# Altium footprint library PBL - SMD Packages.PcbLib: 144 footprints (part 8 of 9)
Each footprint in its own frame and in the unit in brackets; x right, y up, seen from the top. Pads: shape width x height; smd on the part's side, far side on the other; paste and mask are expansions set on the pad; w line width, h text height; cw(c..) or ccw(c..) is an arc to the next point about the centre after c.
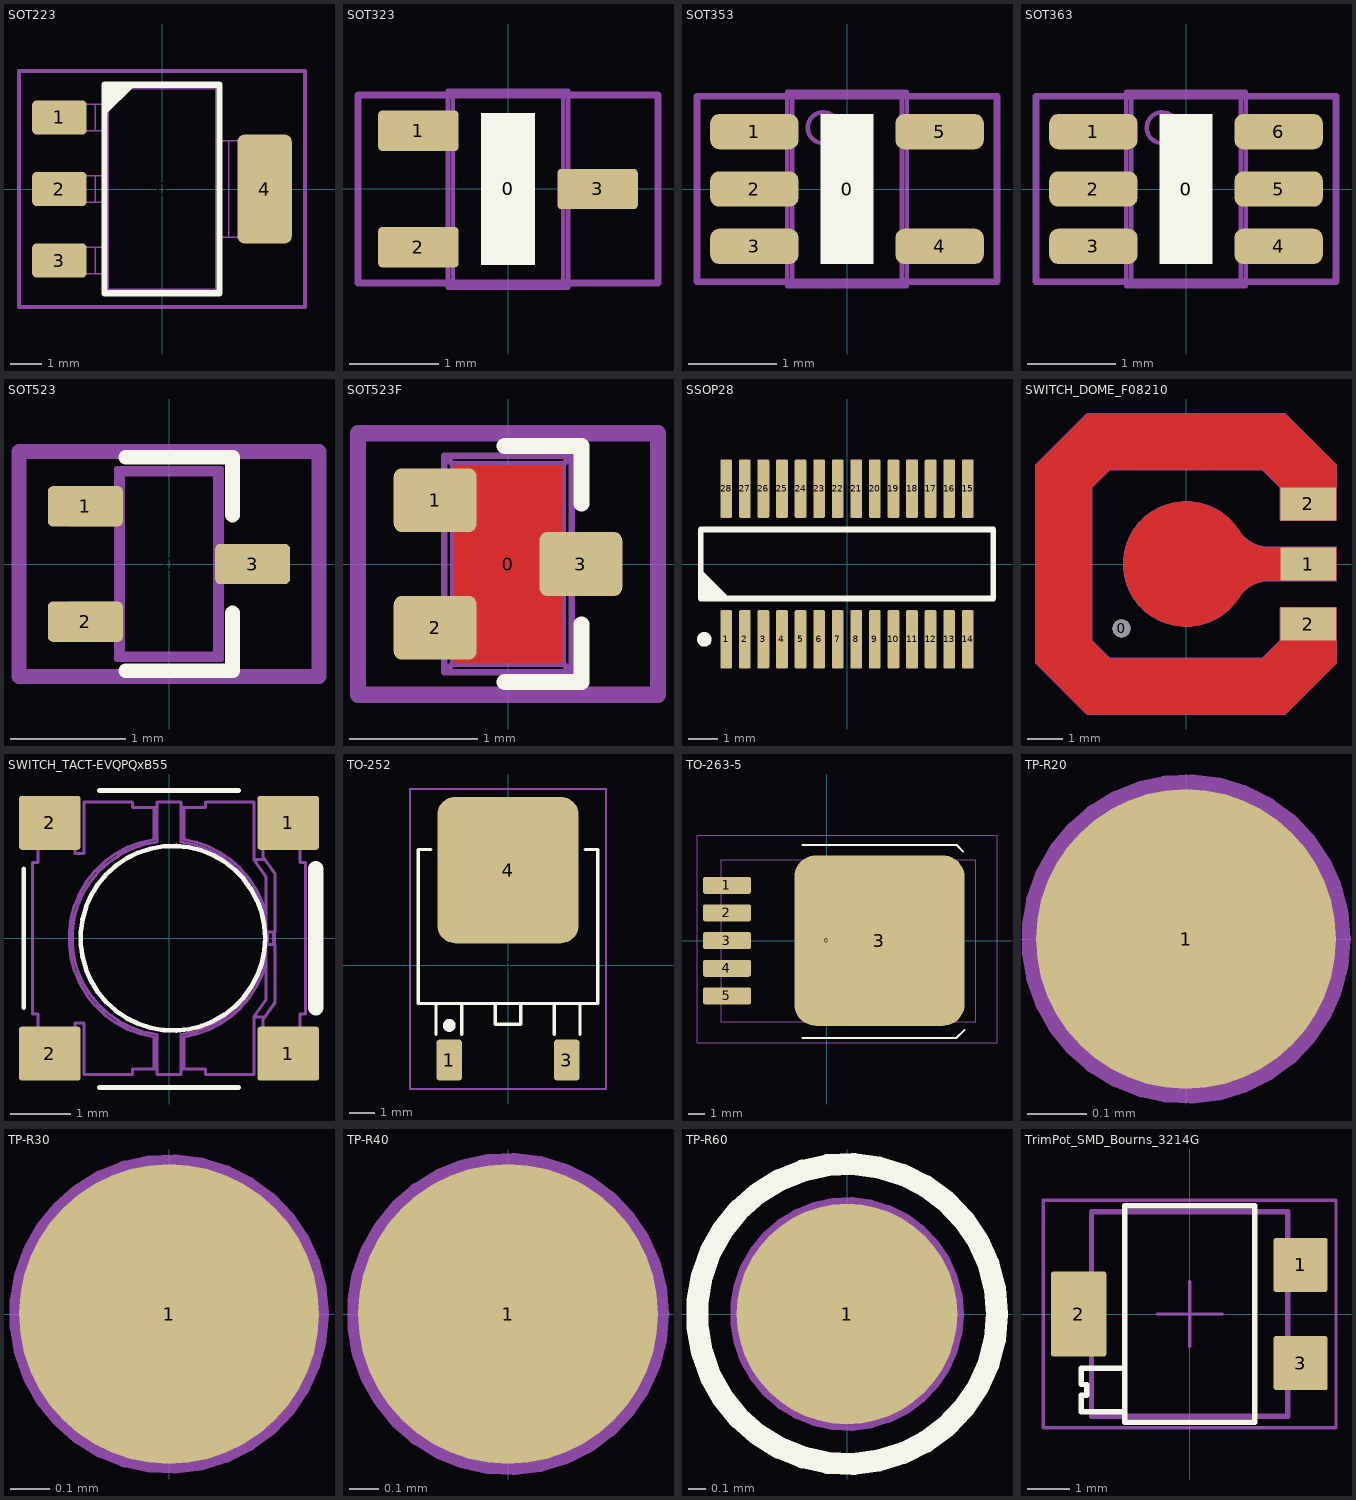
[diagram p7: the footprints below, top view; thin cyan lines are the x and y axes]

## SOT223 [mm] "SOT223 /SC-73"
height 1.524
pads (5):
  round 1 on Mech15: 0(0,0)
  rrect25% 1.75x1.1 smd: 1(-3.3,2.3) 2(-3.3,0) 3(-3.3,-2.3)
  rrect25% 1.75x3.5 smd: 4(3.3,0)
Top Overlay:
  region: -1.85,3.35 -0.85,3.35 -1.85,2.35
  lines w0.2: -1.85,-3.35 1.85,-3.35 1.85,3.35 -1.85,3.35 -1.85,-3.35
13 - 3D Top Side:
  lines w0.05: -3.186,-2.72 -3.186,-1.88 ; -3.186,-0.42 -3.186,0.42 ; -3.186,1.88 -3.186,2.72 ; -3.062,-2.72 -3.062,-1.88 ; -3.062,-0.42 -3.062,0.42 ; -3.062,1.88 -3.062,2.72 ; -2.506,-2.72 -2.506,-1.88 ; -2.506,-0.42 -2.506,0.42 ; -2.506,1.88 -2.506,2.72 ; -2.152,-2.72 -2.152,-1.88 ; -2.152,-0.42 -2.152,0.42 ; -2.152,1.88 -2.152,2.72 ; -1.85,-2.72 -1.85,-3.35 ; -1.85,-1.88 -1.85,-0.42 ; -1.85,0.42 -1.85,1.88 ; -1.85,2.72 -1.85,3.35 ; 1.85,-1.55 1.85,-3.35 ; 1.85,1.55 1.85,3.35 ; 2.152,-1.55 2.152,1.55 ; 2.506,-1.55 2.506,1.55 ; 3.062,-1.55 3.062,1.55 ; 3.186,-1.55 3.186,1.55 ; -1.85,-3.35 1.85,-3.35 ; -1.85,-3.35 -1.731,-3.231 ; -1.85,3.35 1.85,3.35 ; -1.85,3.35 -1.731,3.231 ; -1.731,-3.231 -1.731,3.231 ; -1.731,-3.231 1.731,-3.231 ; -1.731,3.231 1.731,3.231 ; 1.731,-3.231 1.731,3.231 ; 1.731,-3.231 1.85,-3.35 ; 1.731,3.231 1.85,3.35 ; -3.65,-2.72 -1.829,-2.72 -1.829,-1.88 -3.65,-1.88 -3.65,-2.72 ; -3.65,-0.42 -1.829,-0.42 -1.829,0.42 -3.65,0.42 -3.65,-0.42 ; -3.65,1.88 -1.829,1.88 -1.829,2.72 -3.65,2.72 -3.65,1.88 ; 1.829,-1.55 1.829,1.55 3.65,1.55 3.65,-1.55 1.829,-1.55
15 - Top Courtyards:
  lines w0.127: -4.6,-3.8 4.6,-3.8 4.6,3.8 -4.6,3.8 -4.6,-3.8
3D body "SOT223-4.STEP": height 1.8, standoff 0, extent -3.65,-3.35 3.65,3.35

## SOT323 [mm] "Small outline 2.1mm L x 1.25mm W x 1.1mm H; 3 lead SC70, EIAJ SC-70, SOT323"
height 1.1
pads (4):
  round 0.5 on Mech15: 0(0,0)
  rrect20% 0.9x0.45 smd: 1(-1,0.65) 2(-1,-0.65) 3(1,0)
Top Overlay:
  rectangle: -0.3,-0.85 0.3,0.85
  text "." at -1.875,0.65 h0.1
13 - 3D Top Side:
  lines w0.05: -1.028,-0.8 -1.028,-0.5 ; -1.028,0.5 -1.028,0.8 ; -0.937,-0.8 -0.937,-0.5 ; -0.937,0.5 -0.937,0.8 ; -0.925,-0.8 -0.925,-0.5 ; -0.925,0.5 -0.925,0.8 ; 0.925,-0.15 0.925,0.15 ; 0.937,-0.15 0.937,0.15 ; 1.028,-0.15 1.028,0.15 ; -0.675,-1.1 0.675,-1.1 ; -0.675,-1.1 -0.675,1.1 ; -0.675,-1.1 -0.619,-1.044 ; -0.675,1.1 0.675,1.1 ; -0.675,1.1 -0.619,1.043 ; -0.619,-1.044 0.619,-1.044 ; -0.619,-1.044 -0.619,1.043 ; -0.619,1.043 0.619,1.043 ; 0.619,-1.044 0.675,-1.1 ; 0.619,-1.044 0.619,1.043 ; 0.619,1.043 0.675,1.1 ; 0.675,-1.1 0.675,1.1 ; -1.2,-0.8 -1.2,-0.5 -0.654,-0.5 -0.654,-0.8 -1.2,-0.8 ; -1.2,0.5 -1.2,0.8 -0.654,0.8 -0.654,0.5 -1.2,0.5 ; 0.654,-0.15 1.2,-0.15 1.2,0.15 0.654,0.15 0.654,-0.15
15 - Top Courtyards:
  lines w0.076: -1.675,-1.05 -1.675,1.05 1.675,1.05 1.675,-1.05 -1.675,-1.05
3D body "SOT323.STEP": height 1.1, standoff 0, extent -1.2,-1.1 1.2,1.1

## SOT353 [mm] "Small outline 2.1mm L x 1.25mm W x 1mm H; 5LD SC-70; SC-88A"
height 1.1
pads (6):
  round 0.5 on Mech15: 0(0,0)
  rrect50% 1x0.4 smd: 1(-1.05,0.65) 2(-1.05,0) 3(-1.05,-0.65) 4(1.05,-0.65) 5(1.05,0.65)
Top Overlay:
  rectangle: -0.3,-0.85 0.3,0.85
  text "." at -2.025,0.65 h0.1
Top Solder:
  rectangle: -1.397,-0.762 -0.635,0.762
13 - 3D Top Side:
  circle w0.05: c-0.27,0.695 r0.175
  lines w0.05: -1.028,-0.8 -1.028,-0.5 ; -1.028,-0.15 -1.028,0.15 ; -1.028,0.5 -1.028,0.8 ; -0.937,-0.8 -0.937,-0.5 ; -0.937,-0.15 -0.937,0.15 ; -0.937,0.5 -0.937,0.8 ; -0.925,-0.8 -0.925,-0.5 ; -0.925,-0.15 -0.925,0.15 ; -0.925,0.5 -0.925,0.8 ; 0.925,-0.8 0.925,-0.5 ; 0.925,0.5 0.925,0.8 ; 0.937,-0.8 0.937,-0.5 ; 0.937,0.5 0.937,0.8 ; 1.028,-0.8 1.028,-0.5 ; 1.028,0.5 1.028,0.8 ; -0.675,-1.1 0.675,-1.1 ; -0.675,-1.1 -0.675,1.1 ; -0.675,-1.1 -0.619,-1.044 ; -0.675,1.1 0.675,1.1 ; -0.675,1.1 -0.619,1.044 ; -0.619,-1.044 0.619,-1.044 ; -0.619,-1.044 -0.619,1.044 ; -0.619,1.044 0.619,1.044 ; 0.619,-1.044 0.675,-1.1 ; 0.619,-1.044 0.619,1.044 ; 0.619,1.044 0.675,1.1 ; 0.675,-1.1 0.675,1.1 ; -1.2,-0.8 -1.2,-0.5 -0.654,-0.5 -0.654,-0.8 -1.2,-0.8 ; -1.2,-0.15 -1.2,0.15 -0.654,0.15 -0.654,-0.15 -1.2,-0.15 ; -1.2,0.5 -1.2,0.8 -0.654,0.8 -0.654,0.5 -1.2,0.5 ; 0.654,-0.8 1.2,-0.8 1.2,-0.5 0.654,-0.5 0.654,-0.8 ; 0.654,0.5 1.2,0.5 1.2,0.8 0.654,0.8 0.654,0.5
15 - Top Courtyards:
  lines w0.076: -1.7,-1.05 1.7,-1.05 1.7,1.05 -1.7,1.05 -1.7,-1.05
3D body "SOT353.STEP": height 1.1, standoff 0, extent -1.2,-1.1 1.2,1.1

## SOT363 [mm] "Small outline 2.1mm L x 1.25mm W x 1mm H"
height 1
pads (7):
  round 0.5 on Mech15: 0(0,0)
  rrect50% 1x0.4 smd: 1(-1.05,0.65) 2(-1.05,0) 3(-1.05,-0.65) 4(1.05,-0.65) 5(1.05,0) 6(1.05,0.65)
Top Overlay:
  rectangle: -0.3,-0.85 0.3,0.85
  text "." at -2.025,0.65 h0.1
Top Solder:
  region: 1.397,0.762 0.635,0.762 0.635,-0.762 1.397,-0.762
  rectangle: -1.397,-0.762 -0.635,0.762
13 - 3D Top Side:
  circle w0.05: c-0.27,0.695 r0.175
  lines w0.05: -1.028,-0.8 -1.028,-0.5 ; -1.028,-0.15 -1.028,0.15 ; -1.028,0.5 -1.028,0.8 ; -0.937,-0.8 -0.937,-0.5 ; -0.937,-0.15 -0.937,0.15 ; -0.937,0.5 -0.937,0.8 ; -0.925,-0.8 -0.925,-0.5 ; -0.925,-0.15 -0.925,0.15 ; -0.925,0.5 -0.925,0.8 ; 0.925,-0.8 0.925,-0.5 ; 0.925,-0.15 0.925,0.15 ; 0.925,0.5 0.925,0.8 ; 0.937,-0.8 0.937,-0.5 ; 0.937,-0.15 0.937,0.15 ; 0.937,0.5 0.937,0.8 ; 1.028,-0.8 1.028,-0.5 ; 1.028,-0.15 1.028,0.15 ; 1.028,0.5 1.028,0.8 ; -0.675,-1.1 -0.619,-1.044 ; -0.675,-1.1 -0.675,1.1 ; -0.675,-1.1 0.675,-1.1 ; -0.675,1.1 -0.619,1.044 ; -0.675,1.1 0.675,1.1 ; -0.619,-1.044 -0.619,1.044 ; -0.619,-1.044 0.619,-1.044 ; -0.619,1.044 0.619,1.044 ; 0.619,-1.044 0.619,1.044 ; 0.619,-1.044 0.675,-1.1 ; 0.619,1.044 0.675,1.1 ; 0.675,-1.1 0.675,1.1 ; -1.2,-0.8 -0.654,-0.8 -0.654,-0.5 -1.2,-0.5 -1.2,-0.8 ; -1.2,-0.15 -0.654,-0.15 -0.654,0.15 -1.2,0.15 -1.2,-0.15 ; -1.2,0.5 -0.654,0.5 -0.654,0.8 -1.2,0.8 -1.2,0.5 ; 0.654,-0.8 0.654,-0.5 1.2,-0.5 1.2,-0.8 0.654,-0.8 ; 0.654,-0.15 0.654,0.15 1.2,0.15 1.2,-0.15 0.654,-0.15 ; 0.654,0.5 0.654,0.8 1.2,0.8 1.2,0.5 0.654,0.5
15 - Top Courtyards:
  lines w0.076: -1.7,-1.05 1.7,-1.05 1.7,1.05 -1.7,1.05 -1.7,-1.05
3D body "SOT363.STEP": height 1.1, standoff 0, extent -1.2,-1.1 1.2,1.1

## SOT523 [mm] "3 Lead SC75; EIAJ-SC75; SOT523; SOT416?"
height 0.9
pads (4):
  round 0.254 on Mech15: 0(0,0)
  rrect25% 0.65x0.35 smd: 1(-0.725,0.5) 2(-0.725,-0.5) 3(0.725,0)
Top Overlay:
  lines w0.127: -0.375,-0.925 0.55,-0.925 0.55,-0.425 ; -0.375,0.925 0.55,0.925 0.55,0.425
  text "." at -1.455,0.5 h0.05
13 - 3D Top Side:
  lines w0.05: -0.669,-0.65 -0.669,-0.35 ; -0.669,0.35 -0.669,0.65 ; -0.623,-0.65 -0.623,-0.35 ; -0.623,0.35 -0.623,0.65 ; -0.61,-0.65 -0.61,-0.35 ; -0.61,0.35 -0.61,0.65 ; 0.61,-0.15 0.61,0.15 ; 0.623,-0.15 0.623,0.15 ; 0.669,-0.15 0.669,0.15 ; -0.45,-0.825 0.45,-0.825 ; -0.45,-0.825 -0.45,0.825 ; -0.45,-0.825 -0.408,-0.783 ; -0.45,0.825 0.45,0.825 ; -0.45,0.825 -0.408,0.783 ; -0.408,-0.783 0.408,-0.783 ; -0.408,-0.783 -0.408,0.783 ; -0.408,0.783 0.408,0.783 ; 0.408,-0.783 0.45,-0.825 ; 0.408,-0.783 0.408,0.783 ; 0.408,0.783 0.45,0.825 ; 0.45,-0.825 0.45,0.825 ; -0.85,-0.65 -0.85,-0.35 -0.429,-0.35 -0.429,-0.65 -0.85,-0.65 ; -0.85,0.35 -0.85,0.65 -0.429,0.65 -0.429,0.35 -0.85,0.35 ; 0.429,-0.15 0.85,-0.15 0.85,0.15 0.429,0.15 0.429,-0.15
15 - Top Courtyards:
  lines w0.127: -1.3,-0.975 1.3,-0.975 1.3,0.975 -1.3,0.975 -1.3,-0.975
3D body "SOT523.STEP": height 0.9, standoff 0, extent -0.85,-0.825 0.85,0.825

## SOT523F [mm] "3 Lead SC89; EIAJ-SC89; SOT523F"
height 0.8
pads (4):
  round 0.254 on Mech15: 0(0,0)
  rrect25% 0.65x0.5 smd: 1(-0.57,0.5) 2(-0.57,-0.5) 3(0.57,0)
Top Layer:
  pour cut-out: -0.425,0.775 0.425,0.775 0.425,-0.775 -0.425,-0.775
Top Overlay:
  lines w0.127: -0.025,-0.925 0.575,-0.925 0.575,-0.475 ; -0.025,0.925 0.575,0.925 0.575,0.475
  text "." at -1.3,0.5 h0.05
13 - 3D Top Side:
  lines w0.05: -0.499,-0.675 -0.499,-0.849 ; -0.499,-0.325 -0.499,0.325 ; -0.499,0.675 -0.499,0.849 ; 0.499,-0.175 0.499,-0.849 ; 0.499,0.175 0.499,0.849 ; -0.499,-0.849 0.499,-0.849 ; -0.499,-0.849 -0.43,-0.78 ; -0.499,0.849 0.499,0.849 ; -0.499,0.849 -0.43,0.78 ; -0.43,-0.78 0.43,-0.78 ; -0.43,-0.78 -0.43,0.78 ; -0.43,0.78 0.43,0.78 ; 0.43,-0.78 0.43,0.78 ; 0.43,-0.78 0.499,-0.849 ; 0.43,0.78 0.499,0.849 ; -0.85,-0.675 -0.85,-0.325 -0.483,-0.325 -0.483,-0.675 -0.85,-0.675 ; -0.85,0.325 -0.85,0.675 -0.483,0.675 -0.483,0.325 -0.85,0.325 ; 0.483,-0.175 0.85,-0.175 0.85,0.175 0.483,0.175 0.483,-0.175
15 - Top Courtyards:
  lines w0.127: -1.175,-1.025 1.175,-1.025 1.175,1.025 -1.175,1.025 -1.175,-1.025
3D body "SOT523F.STEP": height 0.8, standoff 0, extent -0.85,-0.849 0.85,0.849

## SSOP28 [mm] "SSOP; 28 Leads; Body Width 3.9 mm; Pitch 0.635 mm"
height 1.75
pads (28):
  rrect25% 0.4x2 smd: 1(-4.127,-2.575) 2(-3.492,-2.575) 3(-2.857,-2.575) 4(-2.222,-2.575) 5(-1.587,-2.575) 6(-0.953,-2.575) 7(-0.318,-2.575) 8(0.318,-2.575) 9(0.953,-2.575) 10(1.587,-2.575) 11(2.222,-2.575) 12(2.857,-2.575) 13(3.492,-2.575) 14(4.127,-2.575) 15(4.127,2.575) 16(3.492,2.575) 17(2.857,2.575) 18(2.222,2.575) 19(1.587,2.575) 20(0.953,2.575) 21(0.318,2.575) 22(-0.318,2.575) 23(-0.953,2.575) 24(-1.587,2.575) 25(-2.222,2.575) 26(-2.857,2.575) 27(-3.492,2.575) 28(-4.127,2.575)
Top Overlay:
  circle w0.25: c-4.878,-2.575 r0.125
  region: -5,-1.175 -5,-0.175 -4,-1.175
  lines w0.2: -5,-1.175 5,-1.175 5,1.175 -5,1.175 -5,-1.175

## SWITCH_DOME_F08210 [mm] "Snaptron F08210 dome switch"
height 0.5
pads (4):
  round 0.508 hole 0.508 unplated: 0(-1.8,-1.8)
  rect 1.55x0.92 smd paste-0.8: 1(3.415,0) 2(3.415,-1.68) 2(3.415,1.68)
Top Layer:
  region: -2.77,-4.19 -4.19,-2.77 -4.19,2.77 -2.77,4.19 2.77,4.19 4.19,2.77 4.19,1.22 2.64,1.22 2.64,2.128 2.128,2.64 -2.128,2.64 -2.64,2.128 -2.64,-2.128 -2.128,-2.64 2.128,-2.64 2.64,-2.128 2.64,-1.22 4.19,-1.22 4.19,-2.77 2.77,-4.19
  region: 1.472,-0.927 1.372,-1.086 1.109,-1.354 0.795,-1.559 0.444,-1.693 0.073,-1.749 -0.302,-1.724 -0.663,-1.62 -0.993,-1.441 -1.278,-1.196 -1.503,-0.896 -1.66,-0.555 -1.74,-0.188 -1.74,0.188 -1.66,0.555 -1.503,0.896 -1.278,1.196 -0.993,1.441 -0.663,1.62 -0.302,1.724 0.073,1.749 0.444,1.693 0.795,1.559 1.109,1.354 1.372,1.086 1.472,0.927 1.546,0.825 1.729,0.652 1.949,0.531 2.193,0.468 2.319,0.46 4.19,0.46 4.19,-0.46 2.319,-0.46 2.193,-0.468 1.949,-0.531 1.729,-0.652 1.546,-0.825
Mechanical 3:
  lines w0.05: -4.19,-2.77 -4.19,2.77 -2.77,4.19 2.77,4.19 4.19,2.77 4.19,1.22 2.64,1.22 2.64,2.128 2.128,2.64 -2.128,2.64 -2.64,2.128 -2.64,-2.128 -2.128,-2.64 2.128,-2.64 2.64,-2.128 2.64,-1.22 4.19,-1.22 4.19,-2.77 2.77,-4.19 -2.77,-4.19 -4.19,-2.77 ; 1.472,-0.927 cw(c0,0) 1.472,0.927 ccw(c2.319,1.46) 2.319,0.46 4.19,0.46 4.19,-0.46 2.319,-0.46 ccw(c2.319,-1.46) 1.472,-0.927
3D body "Snap Dome F08210.STEP": height 0.48, standoff 0, extent -3.546,-3.546 3.546,3.546

## SWITCH_TACT-EVQPQxB55 [mil] "Panasonic SMD tact switch 4.5x4.5x0.55mm, EVQPQxB55"
height 21.65
pads (4):
  rrect10% 40x35 smd: 1(77.5,-75) 1(77.5,75) 2(-77.5,-75) 2(-77.5,75)
Top Overlay:
  circle w3: c2.5,0 r60
  lines w3: -94.5,-45.28 -94.5,45.28 ; -45.28,-97 45.28,-97 ; -45.28,96 45.28,96
  lines w10: 95.5,-45.28 95.5,45.28
13 - 3D Top Side:
  lines w1.97: -85.04,-84.12 -61.02,-84.12 ; -85.04,-79.15 -61.02,-79.15 ; -85.04,-77.22 -61.02,-77.22 ; -85.04,-68.45 -61.02,-68.45 ; -85.04,-66.52 -61.02,-66.52 ; -85.04,-62.25 -61.02,-62.25 ; -85.04,-58.68 -61.02,-58.68 ; -85.04,58.68 -61.02,58.68 ; -85.04,62.25 -61.02,62.25 ; -85.04,66.52 -61.02,66.52 ; -85.04,68.45 -61.02,68.45 ; -85.04,77.22 -61.02,77.22 ; -85.04,79.15 -61.02,79.15 ; -85.04,84.12 -61.02,84.12 ; -9.84,-85.04 -9.84,-64.21 cw(c0,0) -9.84,64.21 -9.84,85.04 ; -7.87,-85.04 -23.62,-85.04 -23.62,-88.58 -55.12,-88.58 -55.12,-55.12 -61.02,-55.12 -61.02,-86.61 -85.04,-86.61 -85.04,-49.21 -88.58,-49.21 -88.58,49.21 -85.04,49.21 -85.04,86.61 -61.02,86.61 -61.02,55.12 -55.12,55.12 -55.12,88.58 -23.62,88.58 -23.62,85.04 -7.87,85.04 ; -7.87,-62.5 -7.87,-88.58 7.87,-88.58 7.87,-62.5 ; -7.87,62.5 -7.87,88.58 7.87,88.58 7.87,62.5 ; -7.81,-62.51 cw(c0,0) -7.81,62.51 ; 7.81,-62.51 ccw(c0,0) 7.81,62.51 ; 7.87,-85.04 23.62,-85.04 23.62,-88.58 55.12,-88.58 55.12,-51.29 62.99,-40.04 62.99,40.04 55.12,51.29 55.12,88.58 23.62,88.58 23.62,85.04 7.87,85.04 ; 9.84,-85.04 9.84,-64.21 ccw(c0,0) 62.99,-15.87 ; 9.84,85.04 9.84,64.21 cw(c0,0) 62.99,15.87 ; 55.19,-51.18 62.4,-51.18 ; 55.19,51.18 62.4,51.18 ; 61.02,-84.12 85.04,-84.12 ; 61.02,-79.15 85.04,-79.15 ; 61.02,-77.22 85.04,-77.22 ; 61.02,-68.45 85.04,-68.45 ; 61.02,-66.52 85.04,-66.52 ; 61.02,-62.25 85.04,-62.25 ; 61.02,-58.68 85.04,-58.68 ; 61.02,58.68 85.04,58.68 ; 61.02,62.25 85.04,62.25 ; 61.02,66.52 85.04,66.52 ; 61.02,68.45 85.04,68.45 ; 61.02,77.22 85.04,77.22 ; 61.02,79.15 85.04,79.15 ; 61.02,84.12 85.04,84.12 ; 64.09,-3.94 64.09,3.94 ; 67.8,-3.94 67.8,3.94 ; 68.44,-3.94 68.44,3.94 ; 61.02,-86.61 85.04,-86.61 85.04,-49.21 88.58,-49.21 88.58,49.21 85.04,49.21 85.04,86.61 61.02,86.61 61.02,53.15 68.9,41.9 68.9,3.94 63.45,3.94 63.45,-3.94 68.9,-3.94 68.9,-41.9 61.02,-53.15 61.02,-86.61
3D body "TACT_EVQ-PQHB55.STEP": height 21.65, standoff 0, extent -88.57,-88.58 88.59,88.59

## TO-252 [mm] "D-PAK/TO-252-AA; 3 Leads (1 Cropped); Body 10.3 (inc. leads) x 6.7 mm (LxW max)"
height 2.38
pads (4):
  round 0.5 on Mech15: 0(0,0)
  rrect25% 1x1.6 smd: 1(-2.285,-3.7) 3(2.285,-3.7)
  rrect25% 5.5x5.7 smd: 4(0,3.7)
Top Overlay:
  circle w0.25: c-2.285,-2.35 r0.125
  lines w0.127: -3,4.5 -3.5,4.5 -3.5,-1.5 3.5,-1.5 3.5,4.5 3,4.5 ; -2.8,-2.7 -2.8,-1.5 -1.8,-1.5 -1.8,-2.7 ; 1.8,-2.7 1.8,-1.5 2.8,-1.5 2.8,-2.7 ; -0.5,-2.3 -0.5,-1.5 0.5,-1.5 0.5,-2.3 -0.5,-2.3
15 - Top Courtyards:
  lines w0.076: -3.81,-4.826 -3.81,6.858 3.81,6.858 3.81,-4.826 -3.81,-4.826
3D body "DPAK.stp": height 2.31, standoff 0, extent -3.3,-3.951 3.3,5.762

## TO-263-5 [mm] "D-PAK/TO-263-5; 5 Leads; Body 14.4 (inc. leads) x 10.4 mm (LxW max)"
height 4.65
pads (7):
  round 0.5 on Mech15: 0(0,0)
  rrect25% 2.95x1.05 smd: 1(-6.15,3.41) 2(-6.15,1.705) 3(-6.15,0) 4(-6.15,-1.705) 5(-6.15,-3.41)
  rrect25% 10.5x10.5 smd: 3(3.25,0)
Top Overlay:
  lines w0.127: -1.5,-6 8,-6 8.5,-5.5 ; -1.5,5.9 8,5.9 8.4,5.5
13 - 3D Top Side:
  lines w0.076: -6.49,-5 -6.49,5 9.18,5 9.18,-5 -6.49,-5
15 - Top Courtyards:
  lines w0.076: -8,-6.3 -8,6.5 10.5,6.5 10.5,-6.3 -8,-6.3
3D body "TO-263-5.stp": height 4.56, standoff 0, extent -6.727,-5.08 7.288,5.08

## TP-R20 [mil]
pads (1):
  round 20 smd paste-30 mask+3: 1(0,0)
13 - 3D Top Side:
  circle w1.97: c0,0 r10
3D body: height -3, standoff -5, extent -10.91,-10.98 11,10.98

## TP-R30 [mil]
pads (1):
  round 30 smd paste-30 mask+3: 1(0,0)
13 - 3D Top Side:
  circle w1.97: c0,0 r15
3D body: height 10, standoff 0, extent -17.86,-17.96 18,17.97

## TP-R40 [mil]
pads (1):
  round 40 smd paste-40: 1(0,0)
13 - 3D Top Side:
  circle w3: c0,0 r20
3D body: height 10, standoff 0, extent -19.84,-19.96 20,19.96

## TP-R60 [mm]
pads (1):
  round 1.27 smd paste-1.27: 1(0,0)
Top Overlay:
  circle w0.127: c0,0 r0.864
13 - 3D Top Side:
  circle w0.076: c0,0 r0.635
3D body: height 0.25, standoff 0, extent -0.756,-0.76 0.762,0.761

## TrimPot_SMD_Bourns_3214G [mm] "Bourns- 3214G - TRIMMER"
height 3.81
pads (3):
  rrect10% 1.27x1.27 smd: 1(2.6,1.15) 3(2.6,-1.15)
  rrect10% 1.3x2 smd: 2(-2.6,0)
Top Overlay:
  lines w0.127: -1.524,-2.286 -2.54,-2.286 -2.54,-1.905 -2.413,-1.905 -2.413,-1.651 -2.54,-1.651 -2.54,-1.27 -1.524,-1.27 ; -1.524,-2.54 1.524,-2.54 1.524,2.54 -1.524,2.54 -1.524,-2.54
13 - 3D Top Side:
  lines w0.127: -2.3,-2.4 -2.3,2.4 2.3,2.4 2.3,-2.4 -2.3,-2.4
15 - Top Courtyards:
  lines w0.076: -0.762,0 0.762,0 ; 0,-0.762 0,0.762 ; -3.429,-2.667 -3.429,2.667 3.429,2.667 3.429,-2.667 -3.429,-2.667
3D body "Trimpot 3214G.stp": height 3.9, standoff 0.2, extent -2.3,-2.4 2.3,2.4
3D body: height 0.2, standoff 0, extent -3,-0.65 -1.6,0.65
3D body: height 0.2, standoff 0, extent 1.6,0.7 3,1.6
3D body: height 0.2, standoff 0, extent 1.6,-1.6 3,-0.7
3D body: height 3.9, standoff 3.9, extent -2.3,-2.4 2.3,2.4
